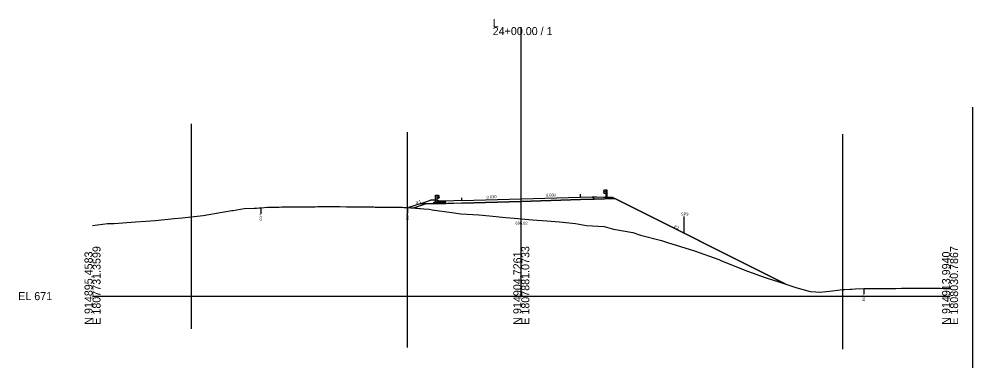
# Model space of a CAD drawing. Extents: x -26 to 1352, y -510 to 9596.
# Drawn here: x 974.3 to 1308, y -25.1 to 96.9 of the extents above; entities that cross this region are included whole.
import ezdxf

# ---------------------------------------------------------------- set-up
doc = ezdxf.new("R2010")
doc.units = 0
for name, color, linetype in [('Exist Cross Section Cell', 7, 'Continuous'), ('Exist XS Center Line Elevation Label', 7, 'Continuous'), ('Exist XS Ground Line', 7, 'Continuous'), ('Old_Level_10', 7, 'Continuous'), ('Prop XS Earthwork Shape', 7, 'Continuous'), ('Prop XS EOT Tick Mark', 7, 'Continuous'), ('Prop XS Exc Vertical Line 1', 7, 'Continuous'), ('Prop XS Exc Vertical Line 2', 7, 'Continuous'), ('Prop XS Exc Vertical Line 3', 7, 'Continuous'), ('Prop XS Exc Vertical Line 4', 7, 'Continuous'), ('Prop XS Finish Grade', 7, 'Continuous'), ('Prop XS Finish Grade Earthwork', 7, 'Continuous'), ('Prop XS Finish Grade Paved Shoulder', 7, 'Continuous'), ('Prop XS Finish Grade Pavement', 7, 'Continuous'), ('Prop XS Guardrail', 7, 'Continuous'), ('Prop XS Hydro Fill Slope Data', 7, 'Continuous'), ('Prop XS Pvmt Edge Slope', 7, 'Continuous'), ('Prop XS SE Text', 7, 'Continuous'), ('Prop XS Side Slope Text', 7, 'Continuous'), ('Prop XS Subgrade Earthwork', 7, 'Continuous'), ('Typical Curb CELL', 7, 'Continuous')]:
    doc.layers.add(name, color=color, linetype=linetype)

msp = doc.modelspace()

# ---------------------------------------------------------------- linework, layer by layer
at = {"layer": 'Exist Cross Section Cell'}
for p, q in [((1150, 0), (1150, 94.1)), ((1000, 0), (1150, 0)), ((1150, 0), (1300, 0))]:
    msp.add_line(p, q, dxfattribs=at)
at = {"layer": 'Exist XS Ground Line'}
msp.add_lwpolyline([(1000, 24.72), (1005.21, 25.35), (1005.8, 25.38), (1007.59, 25.46), (1015.06, 25.93), (1018.68, 26.23), (1021.87, 26.51), (1028.69, 27.11), (1031.31, 27.38), (1038.71, 28.2), (1040.74, 28.57), (1048.73, 29.9), (1049.19, 29.97), (1053.03, 30.65), (1056.58, 30.8), (1057.31, 30.82), (1058.33, 30.91), (1058.75, 30.88), (1058.84, 30.89), (1059.04, 30.9), (1061.26, 31.08), (1061.63, 31.09), (1062.45, 31.11), (1063.28, 31.12), (1063.78, 31.13), (1065.34, 31.16), (1066.27, 31.18), (1067.7, 31.19), (1068.77, 31.2), (1069.99, 31.21), (1071.28, 31.22), (1072.42, 31.23), (1073.78, 31.23), (1075.34, 31.25), (1076.29, 31.26), (1076.94, 31.26), (1077.85, 31.28), (1078.8, 31.31), (1079.07, 31.32), (1079.48, 31.34), (1080.92, 31.36), (1081.18, 31.37), (1081.4, 31.37), (1081.63, 31.37), (1083.14, 31.36), (1083.47, 31.35), (1083.96, 31.35), (1085.72, 31.33), (1086.31, 31.32), (1086.57, 31.32), (1088.81, 31.29), (1090.71, 31.28), (1091.32, 31.27), (1091.36, 31.27), (1093.82, 31.25), (1094.38, 31.24), (1095.59, 31.22), (1095.99, 31.21), (1096.33, 31.2), (1098.36, 31.18), (1098.83, 31.17), (1100.72, 31.14), (1101.34, 31.13), (1102.04, 31.12), (1103.84, 31.1), (1104.72, 31.09), (1106.35, 31.07), (1106.93, 31.07), (1107.71, 31.07), (1108.3, 31.06), (1108.85, 31.05), (1109.93, 31.02), (1110.21, 31.01), (1110.35, 31), (1111.3, 30.92), (1111.42, 30.91), (1115.95, 30.57), (1117.77, 30.41), (1118.87, 30.15), (1125.66, 29.27), (1128.89, 28.83), (1135.09, 28.39), (1138.91, 28.03), (1144.53, 27.55), (1148.92, 27.11), (1150, 27.02), (1153.96, 26.7), (1158.94, 26.36), (1163.4, 26.01), (1168.96, 25.37), (1172.83, 24.72), (1178.98, 24.32), (1182.27, 23.42), (1189, 22.28), (1191.7, 21.37), (1199.02, 19.48), (1201.14, 18.74), (1209.04, 16.32), (1210.57, 15.8), (1219.06, 12.81), (1220.01, 12.4), (1229.08, 8.72), (1235.36, 6.57), (1238.88, 5.39), (1239.1, 5.31), (1239.34, 5.23), (1245.98, 3.06), (1251.03, 1.63), (1253.03, 1.47), (1254.47, 1.36), (1258.89, 1.91), (1262.34, 2.29), (1263.07, 2.37), (1265.06, 2.46), (1265.68, 2.49), (1266.85, 2.55), (1269.83, 2.7), (1272.93, 2.71), (1272.97, 2.71), (1273.02, 2.71), (1275.51, 2.71), (1275.71, 2.71), (1277.97, 2.71), (1279.99, 2.71), (1280.5, 2.71), (1281.07, 2.7), (1283.01, 2.74), (1283.78, 2.76), (1284.89, 2.79), (1285.65, 2.78), (1286.86, 2.78), (1287.99, 2.77), (1289.42, 2.77), (1290.52, 2.76), (1291.73, 2.76), (1293.02, 2.75), (1294.42, 2.74), (1295.52, 2.73), (1296.49, 2.73), (1298.03, 2.72), (1298.48, 2.72), (1300, 2.72)], dxfattribs=at)
at = {"layer": 'Old_Level_10'}
for p, q in [((1058.84, 30.89), (1058.84, 28.84)), ((1110.21, 31.01), (1110.21, 28.96)), ((1206.97, 21.96), (1206.97, 27.87)), ((1269.83, 2.7), (1269.83, 0.65))]:
    msp.add_line(p, q, dxfattribs=at)
at = {"layer": 'Prop XS Earthwork Shape'}
for points in [[(1124.3, 32.35), (1119.06, 32.33), (1114.58, 32.33), (1110.52, 30.98), (1112.52, 30.83), (1115.95, 30.57), (1117.77, 30.41), (1118.87, 30.15), (1125.66, 29.27), (1128.89, 28.83), (1135.09, 28.39), (1138.91, 28.03), (1144.53, 27.55), (1148.92, 27.11), (1150, 27.02), (1153.96, 26.7), (1158.94, 26.36), (1163.4, 26.01), (1168.96, 25.37), (1172.83, 24.72), (1178.98, 24.32), (1182.27, 23.42), (1189, 22.28), (1191.7, 21.37), (1199.02, 19.48), (1201.14, 18.74), (1209.04, 16.32), (1210.57, 15.8), (1219.06, 12.81), (1220.01, 12.4), (1229.08, 8.72), (1235.36, 6.57), (1238.88, 5.39), (1239.1, 5.31), (1239.34, 5.23), (1242.49, 4.2), (1182.69, 34.1), (1175.64, 33.89), (1170.75, 33.74), (1150, 33.12), (1129.25, 32.5)], [(1150, 27.02), (1153.96, 26.7), (1158.94, 26.36), (1163.4, 26.01), (1168.96, 25.37), (1172.83, 24.72), (1178.98, 24.32), (1182.27, 23.42), (1189, 22.28), (1191.7, 21.37), (1199.02, 19.48), (1201.14, 18.74), (1209.04, 16.32), (1210.57, 15.8), (1219.06, 12.81), (1220.01, 12.4), (1229.08, 8.72), (1235.36, 6.57), (1238.88, 5.39), (1239.1, 5.31), (1239.34, 5.23), (1242.49, 4.2), (1182.69, 34.1), (1175.64, 33.89), (1170.75, 33.74), (1150, 33.12), (1129.25, 32.5), (1124.3, 32.35), (1116.38, 32.11), (1112.52, 30.83), (1115.95, 30.57), (1117.77, 30.41), (1118.87, 30.15), (1125.66, 29.27), (1128.89, 28.83), (1135.09, 28.39), (1138.91, 28.03), (1144.53, 27.55), (1148.92, 27.11)]]:
    msp.add_lwpolyline(points, close=True, dxfattribs=at)
at = {"layer": 'Prop XS EOT Tick Mark'}
for p, q in [((1129.25, 33.42), (1129.25, 34.42)), ((1170.75, 34.66), (1170.75, 35.66))]:
    msp.add_line(p, q, dxfattribs=at)
at = {"layer": 'Prop XS Exc Vertical Line 1'}
msp.add_line((1034.58, -11.43), (1034.58, 60.23), dxfattribs=at)
at = {"layer": 'Prop XS Exc Vertical Line 2'}
msp.add_line((1110.21, -17.94), (1110.21, 57.29), dxfattribs=at)
at = {"layer": 'Prop XS Exc Vertical Line 3'}
msp.add_line((1262.5, -18.59), (1262.5, 56.64), dxfattribs=at)
at = {"layer": 'Prop XS Exc Vertical Line 4'}
msp.add_line((1307.99, -25.11), (1307.99, 66.09), dxfattribs=at)
at = {"layer": 'Prop XS Finish Grade'}
for p, q in [((1114.58, 32.33), (1118.25, 33.55)), ((1120.56, 33.51), (1118.25, 33.55)), ((1174.75, 34.78), (1176.32, 34.74)), ((1176.32, 34.74), (1178.75, 34.66)), ((1178.75, 34.66), (1181.75, 34.57)), ((1181.75, 34.57), (1182.69, 34.1))]:
    msp.add_line(p, q, dxfattribs=at)
at = {"layer": 'Prop XS Finish Grade Earthwork'}
for p, q in [((1182.69, 34.1), (1242.49, 4.2)), ((1114.58, 32.33), (1110.52, 30.98))]:
    msp.add_line(p, q, dxfattribs=at)
at = {"layer": 'Prop XS Finish Grade Paved Shoulder'}
for p, q in [((1129.25, 33.42), (1123.58, 33.25)), ((1170.75, 34.66), (1174.75, 34.78))]:
    msp.add_line(p, q, dxfattribs=at)
at = {"layer": 'Prop XS Finish Grade Pavement'}
for p, q in [((1129.25, 33.42), (1150, 34.04)), ((1150, 34.04), (1170.75, 34.66))]:
    msp.add_line(p, q, dxfattribs=at)
at = {"layer": 'Prop XS Guardrail'}
for p, q in [((1178.78, 36.92), (1178.75, 36.86)), ((1178.75, 36.86), (1178.78, 36.8)), ((1179.07, 37.12), (1178.78, 36.92)), ((1178.78, 36.8), (1179.07, 36.6)), ((1179.57, 37.12), (1179.07, 37.12)), ((1180.07, 37.12), (1179.57, 37.12)), ((1179.57, 37.12), (1179.57, 34.62)), ((1180.07, 34.62), (1180.07, 37.12)), ((1119.93, 35.32), (1120.43, 35.32)), ((1119.93, 32.82), (1119.93, 35.32)), ((1120.43, 35.32), (1120.93, 35.32)), ((1120.43, 35.32), (1120.43, 32.82)), ((1120.93, 34.18), (1120.43, 34.18)), ((1120.93, 35.32), (1121.22, 35.12)), ((1121.22, 35), (1120.93, 34.8)), ((1120.93, 34.8), (1120.93, 34.7)), ((1120.93, 34.7), (1121.22, 34.5)), ((1121.22, 34.38), (1120.93, 34.18)), ((1121.22, 35.12), (1121.25, 35.06)), ((1121.25, 35.06), (1121.22, 35)), ((1121.22, 34.5), (1121.25, 34.44)), ((1121.25, 34.44), (1121.22, 34.38)), ((1178.78, 36.31), (1178.75, 36.25)), ((1178.75, 36.25), (1178.78, 36.19)), ((1179.07, 36.51), (1178.78, 36.31)), ((1178.78, 36.19), (1179.07, 35.99)), ((1179.07, 36.6), (1179.07, 36.51)), ((1179.07, 35.99), (1179.57, 35.99))]:
    msp.add_line(p, q, dxfattribs=at)
at = {"layer": 'Prop XS Hydro Fill Slope Data'}
msp.add_line((1181.75, 34.57), (1242.49, 4.2), dxfattribs=at)
at = {"layer": 'Prop XS Pvmt Edge Slope'}
for p, q in [((1174.75, 34.78), (1175.64, 33.89)), ((1119.56, 32.83), (1119.06, 32.33)), ((1119.56, 32.83), (1120.56, 32.83))]:
    msp.add_line(p, q, dxfattribs=at)
at = {"layer": 'Prop XS Subgrade Earthwork'}
for p, q in [((1150, 33.12), (1170.75, 33.74)), ((1170.75, 33.74), (1175.64, 33.89)), ((1175.64, 33.89), (1182.69, 34.1)), ((1119.05, 32.33), (1114.58, 32.33)), ((1123.58, 32.33), (1119.05, 32.33)), ((1129.25, 32.5), (1123.58, 32.33)), ((1129.25, 32.5), (1150, 33.12))]:
    msp.add_line(p, q, dxfattribs=at)
at = {"layer": 'Typical Curb CELL'}
for p, q in [((1120.56, 32.83), (1120.56, 33.51)), ((1121.25, 33.16), (1120.56, 33.51)), ((1120.56, 32.83), (1123.58, 32.83)), ((1120.6, 33.13), (1120.75, 33.17)), ((1120.74, 33.08), (1120.6, 33.13)), ((1120.75, 33.17), (1120.74, 33.08)), ((1121.27, 33.05), (1121.17, 32.97)), ((1121.17, 32.97), (1121.33, 32.93)), ((1123.57, 33.25), (1121.25, 33.16)), ((1121.33, 32.93), (1121.27, 33.05)), ((1122.01, 33.1), (1121.98, 32.99)), ((1121.98, 32.99), (1122.1, 32.98)), ((1122.1, 32.98), (1122.01, 33.1)), ((1122.52, 33.05), (1122.41, 32.97)), ((1122.41, 32.97), (1122.58, 32.93)), ((1122.58, 32.93), (1122.52, 33.05)), ((1123.26, 33.1), (1123.22, 32.99)), ((1123.22, 32.99), (1123.35, 32.98)), ((1123.35, 32.98), (1123.26, 33.1)), ((1123.58, 33.25), (1123.58, 33.25)), ((1123.58, 32.83), (1123.58, 33.24))]:
    msp.add_line(p, q, dxfattribs=at)
for centre in [(1120.63, 33.22), (1120.72, 32.94), (1120.84, 32.99), (1121.1, 33.02), (1121.12, 32.97), (1121.3, 32.88), (1121.32, 32.99), (1121.52, 32.95), (1121.56, 33.06), (1121.69, 33.03), (1121.72, 32.91), (1121.78, 32.94), (1121.97, 32.94), (1122.09, 32.99), (1122.19, 32.98), (1122.28, 32.94), (1122.34, 33.08), (1122.35, 33.02), (1122.37, 32.97), (1122.57, 32.99), (1122.77, 32.95), (1122.81, 33.06), (1122.86, 33.03), (1122.94, 33.03), (1122.97, 32.91), (1123.03, 32.94), (1123.09, 33.12), (1123.46, 33.19), (1123.49, 33.07)]:
    msp.add_circle(centre, 0.00802, dxfattribs=at)
msp.add_arc((1123.57, 33.24), 0.0104, 0, 92.048, dxfattribs=at)

# ---------------------------------------------------------------- texts
at = {"layer": 'Exist Cross Section Cell'}
for s, p in [('L', (1140, 94.1)), ('24+00.00 / 1', (1140, 91.3)), ('EL 671', (974, -1.4))]:
    msp.add_text(s, height=2.8, dxfattribs=at).set_placement(p)
for s, p in [('E 1807731.3599', (1002.8, -10)), ('E 1807881.0733', (1152.8, -10)), ('E 1808030.7867', (1302.8, -10)), ('N 914895.4583', (1000, -10)), ('N 914904.7261', (1150, -10)), ('N 914913.9940', (1300, -10))]:
    msp.add_text(s, height=2.8, rotation=90, dxfattribs=at).set_placement(p)
at = {"layer": 'Exist XS Center Line Elevation Label'}
msp.add_text('698.02', height=1, dxfattribs=at).set_placement((1147.96, 25.02))
at = {"layer": 'Old_Level_10'}
for p in [(1059.23, 26.44), (1110.61, 26.56), (1270.22, -1.74)]:
    msp.add_text('EOP', height=0.787, rotation=90, dxfattribs=at).set_placement(p)
msp.add_text('SP9', height=1, dxfattribs=at).set_placement((1205.85, 28.18))
at = {"layer": 'Prop XS SE Text'}
for p in [(1137.88, 34.18), (1158.63, 34.8)]:
    msp.add_text('0.030', height=1, rotation=1.7184, dxfattribs=at).set_placement(p)
at = {"layer": 'Prop XS Side Slope Text'}
for s, rotation, p in [('3:1', 18.4349, (1113.23, 32.13)), ('2:1', 333.4349, (1203.25, 24.12))]:
    msp.add_text(s, height=1, rotation=rotation, dxfattribs=at).set_placement(p)

doc.saveas('drawing.dxf')
